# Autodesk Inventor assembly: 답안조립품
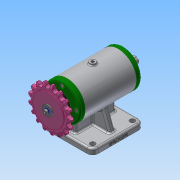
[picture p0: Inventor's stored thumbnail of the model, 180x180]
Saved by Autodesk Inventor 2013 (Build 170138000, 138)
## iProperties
Created: 2019-06
Part Number: 답안조립품
Document SubType Name: Assembly
Designer: Administrator
Author: Administrator
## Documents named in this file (11)
- C:\Users\Administrator\Desktop\490604V1012\답안조립품.iam
- C:\Users\Administrator\Desktop\490604V1012\본체.ipt
- C:\Users\Administrator\Desktop\490604V1012\축.ipt
- C:\Users\Administrator\Desktop\490604V1012\베어링 6203.ipt
- C:\Users\Administrator\Desktop\490604V1012\커버.ipt
- C:\Users\Administrator\Desktop\490604V1012\오일 실 17 30 5.ipt
- C:\Users\Administrator\Desktop\490604V1012\키 4x4x12.ipt
- C:\Users\Administrator\Desktop\490604V1012\볼트 M4.ipt
- C:\Users\Administrator\Desktop\490604V1012\평와셔.ipt
- C:\Users\Administrator\Desktop\490604V1012\스프링와셔.ipt
- C:\Users\Administrator\Desktop\490604V1012\스프로킷.ipt
